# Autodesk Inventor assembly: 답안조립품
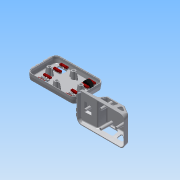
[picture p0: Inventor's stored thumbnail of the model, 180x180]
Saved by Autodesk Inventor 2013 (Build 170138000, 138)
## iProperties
Created: 2015-05
Part Number: 답안조립품
Document SubType Name: Assembly
Designer: Administrator
Author: Administrator
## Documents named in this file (6)
- C:\Documents and Settings\Administrator\바탕 화면\450507V1017\답안조립품.iam
- C:\Documents and Settings\Administrator\바탕 화면\450507V1017\1-본체.ipt
- C:\Documents and Settings\Administrator\바탕 화면\450507V1017\커버.ipt
- C:\Documents and Settings\Administrator\바탕 화면\450507V1017\바퀴.ipt
- C:\Documents and Settings\Administrator\바탕 화면\450507V1017\바퀴고정부.ipt
- C:\Documents and Settings\Administrator\바탕 화면\450507V1017\바퀴고정부_MIR.ipt
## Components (1 placed, 1 different names)
1. 1-본체:1
